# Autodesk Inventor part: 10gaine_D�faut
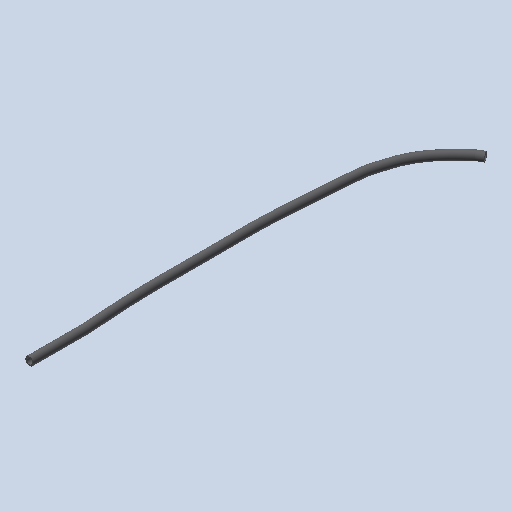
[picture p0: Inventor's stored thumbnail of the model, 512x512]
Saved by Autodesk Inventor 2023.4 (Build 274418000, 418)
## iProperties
Created: 2011-01
Part Number: 10gaine_D�faut
Document SubType Name: Modeling
Designer: eric
Density: 1 g/cm^3
Mass: 4.70572 g
Surface Area: 94.3049 cm^2
Volume: 4.70572 cm^3
Material: Générique
Appearance: Blue
Author: eric
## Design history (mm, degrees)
feature "Base1"
node "Corps solides"
node "Corps surfaciques"
node "Solide1"
